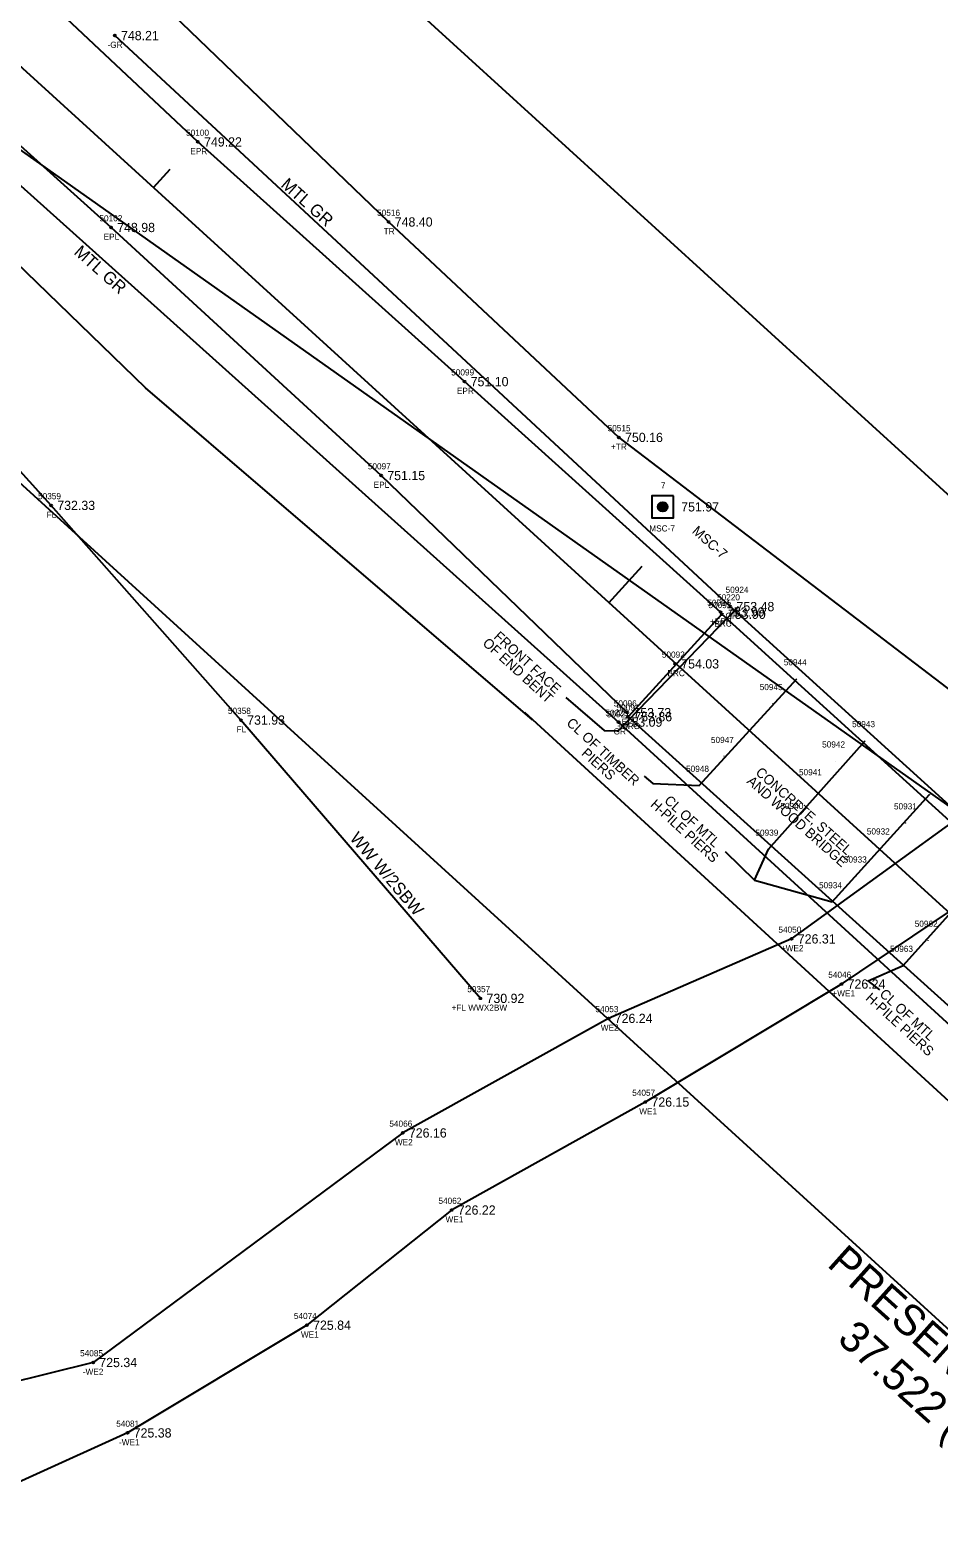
# Model space of a CAD drawing. Extents: x 1378245 to 1381654, y 996521 to 1000567.
# Drawn here: x 1379540.2 to 1379687.6, y 998853.4 to 999097.9 of the extents above; entities that cross this region are included whole.
import ezdxf

# ---------------------------------------------------------------- set-up
doc = ezdxf.new("R2010")
doc.units = 0
for name, color, linetype in [('Default', 7, 'Continuous'), ('RD_EX_Bridge', 7, 'Continuous'), ('RD_EX_Bridge_txCode', 7, 'Continuous'), ('RD_EX_Fence_Other', 7, 'Continuous'), ('RD_EX_Fence_Other_txCode', 7, 'Continuous'), ('RD_EX_GuardRail', 7, 'Continuous'), ('RD_EX_GuardRail_txCode', 7, 'Continuous'), ('RD_EX_H2O', 7, 'Continuous'), ('RD_EX_H2O_txCode', 7, 'Continuous'), ('RD_EX_Road', 7, 'Continuous'), ('RD_EX_Road_txCode', 7, 'Continuous'), ('RD_EX_RW', 7, 'Continuous'), ('RD_EX_RW_TX', 7, 'Continuous'), ('RD_EX_SU_Elec', 7, 'Continuous'), ('RD_EX_TX_Bridge_ELEV', 7, 'Continuous'), ('RD_EX_TX_Fence_Other_ELEV', 7, 'Continuous'), ('RD_EX_TX_GuardRail_ELEV', 7, 'Continuous'), ('RD_EX_TX_H2O_ELEV', 7, 'Continuous'), ('RD_EX_TX_Road_ELEV', 7, 'Continuous'), ('RD_EX_TX_VEG_ELEV', 7, 'Continuous'), ('RD_EX_VEG', 7, 'Continuous'), ('RD_EX_VEG_txCode', 7, 'Continuous'), ('RD_HC_Cl', 7, 'Continuous'), ('RD_HC_Data_Tic', 7, 'Continuous'), ('RD_HC_Survey', 7, 'Continuous'), ('RD_HC_Survey_ELEV', 7, 'Continuous'), ('RD_HC_Survey_txCode', 7, 'Continuous'), ('RD_SMD_Locator', 7, 'Continuous'), ('RD_TX_Misc1', 7, 'Continuous'), ('RD_TX_Misc2', 7, 'Continuous')]:
    doc.layers.add(name, color=color, linetype=linetype)

msp = doc.modelspace()

# ---------------------------------------------------------------- linework, layer by layer
at = {"layer": 'Default'}
for p, q in [((1379655.15, 999004.45), (1379655.14, 999004.45)), ((1379655.15, 999004.45), (1379655.15, 999004.44)), ((1379664.61, 998992.69), (1379664.59, 998992.69)), ((1379664.6, 998992.69), (1379664.6, 998992.68)), ((1379660.7, 998988.67), (1379660.68, 998988.67)), ((1379660.69, 998988.68), (1379660.69, 998988.66)), ((1379635.59, 998984.27), (1379635.57, 998984.27)), ((1379635.58, 998984.28), (1379635.58, 998984.26)), ((1379675.69, 998982.66), (1379675.67, 998982.66)), ((1379675.68, 998982.67), (1379675.68, 998982.65)), ((1379652.78, 998980.09), (1379652.76, 998980.09)), ((1379652.77, 998980.09), (1379652.77, 998980.08)), ((1379670.83, 998979.36), (1379670.81, 998979.36)), ((1379670.82, 998979.37), (1379670.82, 998979.35)), ((1379648.75, 998975.41), (1379648.73, 998975.41)), ((1379648.74, 998975.42), (1379648.74, 998975.4)), ((1379666.78, 998974.85), (1379666.76, 998974.85)), ((1379666.77, 998974.86), (1379666.77, 998974.84)), ((1379686.13, 998973.96), (1379686.11, 998973.96)), ((1379686.12, 998973.97), (1379686.12, 998973.95)), ((1379664.09, 998969.38), (1379664.07, 998969.38)), ((1379664.08, 998969.39), (1379664.08, 998969.38)), ((1379682.2, 998969.32), (1379682.18, 998969.32)), ((1379682.19, 998969.33), (1379682.19, 998969.31)), ((1379660, 998965.05), (1379659.98, 998965.05)), ((1379659.99, 998965.06), (1379659.99, 998965.04)), ((1379678.08, 998965.25), (1379678.06, 998965.25)), ((1379678.07, 998965.26), (1379678.07, 998965.24)), ((1379674.35, 998960.7), (1379674.33, 998960.7)), ((1379674.34, 998960.71), (1379674.34, 998960.69)), ((1379670.31, 998956.52), (1379670.3, 998956.52)), ((1379670.31, 998956.53), (1379670.31, 998956.51)), ((1379685.86, 998950.29), (1379685.86, 998950.27)), ((1379685.87, 998950.28), (1379685.86, 998950.28)), ((1379681.87, 998946.21), (1379681.86, 998946.21)), ((1379681.87, 998946.22), (1379681.87, 998946.2))]:
    msp.add_line(p, q, dxfattribs=at)
at = {"layer": 'RD_EX_Bridge'}
for p, q in [((1379635.58, 998984.27), (1379655.15, 999004.45)), ((1379648.74, 998975.4), (1379664.6, 998992.69)), ((1379659.99, 998965.05), (1379675.68, 998982.66)), ((1379670.31, 998956.52), (1379686.12, 998973.96)), ((1379681.87, 998946.21), (1379697.5, 998963.6))]:
    msp.add_line(p, q, dxfattribs=at)
msp.add_lwpolyline([(1379715.01, 998916.39), (1379729.96, 998932.8), (1379652.41, 999003.17), (1379637.22, 998986.55), (1379715.01, 998916.39)], dxfattribs=at)
at = {"layer": 'RD_EX_Fence_Other'}
msp.add_lwpolyline([(1379613.24, 998940.87), (1379574.4, 998986.01), (1379543.59, 999020.83), (1379505.83, 999062.54), (1379472.56, 999095.44), (1379454.3, 999112.36), (1379373.85, 999187.96), (1379325.25, 999231.37), (1379289.51, 999266.01), (1379255.48, 999295.15), (1379213.9, 999334), (1379169.28, 999374.93), (1379148.65, 999391.69), (1379140.06, 999386.4)], dxfattribs=at)
at = {"layer": 'RD_EX_GuardRail'}
for points in [[(1379497.52, 999109.58), (1379635.64, 998985.68), (1379713.53, 998914.45), (1379759.99, 998873.32)], [(1379777.52, 998892.18), (1379731.47, 998933.97), (1379653.8, 999004.42), (1379553.93, 999097.04)]]:
    msp.add_lwpolyline(points, dxfattribs=at)
at = {"layer": 'RD_EX_H2O'}
for points in [[(1379663.75, 998950.52), (1379692.38, 998971.29), (1379719.04, 999005.74), (1379767.05, 999077.47), (1379820.32, 999142.06), (1379856.78, 999184.17), (1379909.65, 999199.37), (1379968.41, 999216.31), (1380029.43, 999227.41), (1380049.41, 999276.13), (1380067, 999316.44)], [(1379671.83, 998943.2), (1379700.96, 998962.76), (1379729.37, 998999.6)], [(1379663.75, 998950.52), (1379634.04, 998937.63), (1379600.64, 998919.05), (1379550.41, 998881.81), (1379521.39, 998874.62)], [(1379671.83, 998943.2), (1379640, 998924.06), (1379608.58, 998906.54), (1379585.1, 998887.86), (1379555.99, 998870.39), (1379525.83, 998856.73)]]:
    msp.add_lwpolyline(points, dxfattribs=at)
at = {"layer": 'RD_EX_Road'}
for points in [[(1379637.07, 998987.22), (1379597.14, 999025.68), (1379553.31, 999065.91), (1379510.7, 999104.3), (1379468.49, 999142.89), (1379424.88, 999182.89), (1379377.9, 999224.84), (1379333.61, 999264.98), (1379287.28, 999307.21), (1379240.78, 999348.98)], [(1379652.22, 999003.54), (1379610.67, 999040.91), (1379567.41, 999079.79), (1379524.77, 999119.81), (1379481.79, 999158.31), (1379438.69, 999197.69), (1379392.81, 999238.63), (1379346.75, 999280.78), (1379301.8, 999321.66)]]:
    msp.add_lwpolyline(points, dxfattribs=at)
at = {"layer": 'RD_EX_RW'}
for p, q in [((1379446.02, 999244.05), (1379815.63, 998907.31)), ((1379378.68, 999170.13), (1379748.28, 998833.39))]:
    msp.add_line(p, q, dxfattribs=at)
at = {"layer": 'RD_EX_SU_Elec'}
msp.add_lwpolyline([(1378514.25, 999944.12), (1378777.7, 999831.22), (1379190.17, 999461.05), (1379403.33, 999174.04), (1379756.94, 998924.25), (1380051.16, 998659.97), (1380327.91, 998390.65), (1380546.23, 998058.37)], dxfattribs=at)
at = {"layer": 'RD_EX_VEG'}
for p, q in [((1379635.72, 999031.86), (1379746.57, 998947.26)), ((1379716.47, 998899.23), (1379620.44, 998987.26))]:
    msp.add_line(p, q, dxfattribs=at)
for points in [[(1379635.72, 999031.86), (1379598.35, 999066.81), (1379553.67, 999109.8), (1379511.83, 999151.82), (1379464.53, 999192.2), (1379415.99, 999234.77), (1379368.04, 999279.07), (1379324.89, 999312.56), (1379291.58, 999344.45), (1379199.89, 999450.8), (1379227.01, 999457.75)], [(1379621.71, 998986.05), (1379558.91, 999039.89), (1379518.45, 999079.04), (1379470.36, 999123.18), (1379409.67, 999155.52), (1379381.73, 999202.94), (1379345.95, 999233.83), (1379296.88, 999282.18), (1379264.05, 999313.51), (1379229.78, 999344.81), (1379187.41, 999381.54), (1379155.41, 999406.5), (1379144.25, 999379.18), (1379133.7, 999360.09), (1379119.62, 999335.97)]]:
    msp.add_lwpolyline(points, dxfattribs=at)
at = {"layer": 'RD_HC_Cl'}
msp.add_line((1378781.54, 999781.8), (1380217.09, 998473.92), dxfattribs=at)
at = {"layer": 'RD_HC_Data_Tic'}
for p, q in [((1379560.19, 999072.4), (1379562.89, 999075.35)), ((1379634.11, 999005.05), (1379639.5, 999010.96))]:
    msp.add_line(p, q, dxfattribs=at)
at = {"layer": 'RD_HC_Survey'}
for p, q in [((1379642.07, 999020.42), (1379642.07, 999020.78)), ((1379642.1, 999020.34), (1379642.1, 999020.87)), ((1379642.12, 999020.28), (1379642.12, 999020.93)), ((1379642.15, 999020.23), (1379642.15, 999020.98)), ((1379642.17, 999020.18), (1379642.17, 999021.02)), ((1379642.2, 999020.15), (1379642.2, 999021.05)), ((1379642.22, 999020.11), (1379642.22, 999021.09)), ((1379642.25, 999020.08), (1379642.25, 999021.12)), ((1379642.27, 999020.06), (1379642.27, 999021.14)), ((1379642.3, 999020.03), (1379642.3, 999021.17)), ((1379642.32, 999020.01), (1379642.32, 999021.19)), ((1379642.35, 999019.99), (1379642.35, 999021.21)), ((1379642.37, 999019.97), (1379642.37, 999021.23)), ((1379642.4, 999019.95), (1379642.4, 999021.25)), ((1379642.42, 999019.94), (1379642.42, 999021.26)), ((1379642.45, 999019.92), (1379642.45, 999021.28)), ((1379642.47, 999019.91), (1379642.47, 999021.29)), ((1379642.5, 999019.9), (1379642.5, 999021.3)), ((1379642.52, 999019.89), (1379642.52, 999021.32)), ((1379642.55, 999019.88), (1379642.55, 999021.33)), ((1379642.57, 999019.87), (1379642.57, 999021.33)), ((1379642.6, 999019.86), (1379642.6, 999021.34)), ((1379642.62, 999019.85), (1379642.62, 999021.35)), ((1379642.65, 999019.85), (1379642.65, 999021.36)), ((1379642.67, 999019.84), (1379642.67, 999021.36)), ((1379642.7, 999019.83), (1379642.7, 999021.37)), ((1379642.72, 999019.83), (1379642.72, 999021.37)), ((1379642.75, 999019.83), (1379642.75, 999021.37)), ((1379642.77, 999019.83), (1379642.77, 999021.38)), ((1379642.8, 999019.82), (1379642.8, 999021.38)), ((1379642.82, 999019.82), (1379642.82, 999021.38)), ((1379642.85, 999019.82), (1379642.85, 999021.38)), ((1379642.87, 999019.82), (1379642.87, 999021.38)), ((1379642.9, 999019.83), (1379642.9, 999021.38)), ((1379642.92, 999019.83), (1379642.92, 999021.37)), ((1379642.95, 999019.83), (1379642.95, 999021.37)), ((1379642.97, 999019.84), (1379642.97, 999021.36)), ((1379643, 999019.84), (1379643, 999021.36)), ((1379643.02, 999019.85), (1379643.02, 999021.35)), ((1379643.05, 999019.86), (1379643.05, 999021.35)), ((1379643.07, 999019.86), (1379643.07, 999021.34)), ((1379643.1, 999019.87), (1379643.1, 999021.33)), ((1379643.12, 999019.88), (1379643.12, 999021.32)), ((1379643.15, 999019.89), (1379643.15, 999021.31)), ((1379643.17, 999019.9), (1379643.17, 999021.3)), ((1379643.2, 999019.92), (1379643.2, 999021.29)), ((1379643.22, 999019.93), (1379643.22, 999021.27)), ((1379643.25, 999019.95), (1379643.25, 999021.26)), ((1379643.27, 999019.96), (1379643.27, 999021.24)), ((1379643.3, 999019.98), (1379643.3, 999021.22)), ((1379643.32, 999020), (1379643.32, 999021.2)), ((1379643.35, 999020.02), (1379643.35, 999021.18)), ((1379643.37, 999020.05), (1379643.37, 999021.16)), ((1379643.4, 999020.07), (1379643.4, 999021.13)), ((1379643.42, 999020.1), (1379643.42, 999021.1)), ((1379643.45, 999020.13), (1379643.45, 999021.07)), ((1379643.47, 999020.17), (1379643.47, 999021.04)), ((1379643.5, 999020.21), (1379643.5, 999021)), ((1379643.52, 999020.25), (1379643.52, 999020.95)), ((1379643.55, 999020.31), (1379643.55, 999020.9)), ((1379643.57, 999020.38), (1379643.57, 999020.83)), ((1379643.6, 999020.49), (1379643.6, 999020.71))]:
    msp.add_line(p, q, dxfattribs=at)
msp.add_lwpolyline([(1379644.6, 999022.37), (1379641.06, 999022.37), (1379641.06, 999018.83), (1379644.6, 999018.83)], close=True, dxfattribs=at)
msp.add_circle((1379642.83, 999020.6), 0.777, dxfattribs=at)
at = {"layer": 'RD_SMD_Locator'}
for centre, radius in [((1379553.93, 999097.04), 0.15), ((1379567.41, 999079.79), 0.15), ((1379598.35, 999066.81), 0.15), ((1379553.31, 999065.91), 0.15), ((1379610.67, 999040.91), 0.15), ((1379635.72, 999031.86), 0.15), ((1379597.14, 999025.68), 0.15), ((1379543.59, 999020.83), 0.15), ((1379642.83, 999020.6), 0.075), ((1379652.22, 999003.54), 0.15), ((1379652.41, 999003.17), 0.15), ((1379653.8, 999004.42), 0.15), ((1379644.84, 998995.13), 0.15), ((1379574.4, 998986.01), 0.15), ((1379637.07, 998987.22), 0.15), ((1379637.22, 998986.55), 0.15), ((1379635.64, 998985.68), 0.15), ((1379663.75, 998950.52), 0.15), ((1379671.83, 998943.2), 0.15), ((1379613.24, 998940.87), 0.15), ((1379634.04, 998937.63), 0.15), ((1379640, 998924.06), 0.15), ((1379600.64, 998919.05), 0.15), ((1379608.58, 998906.54), 0.15), ((1379585.1, 998887.86), 0.15), ((1379550.41, 998881.81), 0.15), ((1379555.99, 998870.39), 0.15)]:
    msp.add_circle(centre, radius, dxfattribs=at)
at = {"layer": 'RD_TX_Misc1'}
msp.add_line((1379657.72, 998960.05), (1379670.31, 998956.52), dxfattribs=at)
for points in [[(1379627.09, 998989.66), (1379633.34, 998984.31), (1379635.58, 998984.27)], [(1379639.82, 998976.94), (1379641.21, 998975.73), (1379648.74, 998975.4)], [(1379652.98, 998964.68), (1379657.72, 998960.05), (1379659.99, 998965.05)], [(1379678.07, 998942.26), (1379676.16, 998943.72), (1379681.87, 998946.21)]]:
    msp.add_lwpolyline(points, dxfattribs=at)

# ---------------------------------------------------------------- texts
at = {"layer": 'Default'}
for s, p in [('50924', (1379653.03, 999006.65)), ('50944', (1379662.48, 998994.89)), ('50945', (1379658.57, 998990.87)), ('50921', (1379633.75, 998986.47)), ('50943', (1379673.56, 998984.86)), ('50947', (1379650.65, 998982.29)), ('50942', (1379668.7, 998981.56)), ('50948', (1379646.62, 998977.61)), ('50941', (1379664.94, 998977.05)), ('50940', (1379661.92, 998971.58)), ('50931', (1379680.35, 998971.52)), ('50939', (1379657.87, 998967.25)), ('50932', (1379675.95, 998967.45)), ('50933', (1379672.22, 998962.9)), ('50934', (1379668.19, 998958.72)), ('50962', (1379683.72, 998952.48)), ('50963', (1379679.72, 998948.41))]:
    msp.add_text(s, height=1, dxfattribs=at).set_placement(p)
at = {"layer": 'RD_EX_Bridge_txCode'}
for s, p in [('50093', (1379650.25, 999004.17)), ('-BRC', (1379650.75, 999001.17)), ('50092', (1379642.69, 998996.13)), ('BRC', (1379643.59, 998993.13)), ('50091', (1379635.35, 998987.55)), ('+BRC', (1379635.48, 998984.55))]:
    msp.add_text(s, height=1, dxfattribs=at).set_placement(p)
at = {"layer": 'RD_EX_Fence_Other_txCode'}
for s, p in [('50359', (1379541.47, 999021.83)), ('FL', (1379542.86, 999018.83)), ('50358', (1379572.28, 998987.01)), ('FL', (1379573.67, 998984.01)), ('50357', (1379611.12, 998941.87)), ('+FL WWX2BW', (1379608.56, 998938.87))]:
    msp.add_text(s, height=1, dxfattribs=at).set_placement(p)
at = {"layer": 'RD_EX_GuardRail_txCode'}
for s, p in [('-GR', (1379552.74, 999095.04)), ('50220', (1379651.64, 999005.42)), ('GR', (1379653.02, 999002.42)), ('50225', (1379633.52, 998986.68)), ('GR', (1379634.86, 998983.68))]:
    msp.add_text(s, height=1, dxfattribs=at).set_placement(p)
at = {"layer": 'RD_EX_H2O_txCode'}
for s, p in [('54050', (1379661.6, 998951.52)), ('+WE2', (1379662, 998948.52)), ('54046', (1379669.69, 998944.2)), ('+WE1', (1379670.36, 998941.2)), ('54053', (1379631.92, 998938.63)), ('WE2', (1379632.78, 998935.63)), ('54057', (1379637.88, 998925.06)), ('WE1', (1379639.02, 998922.06)), ('54066', (1379598.47, 998920.05)), ('WE2', (1379599.37, 998917.05)), ('54062', (1379606.44, 998907.54)), ('WE1', (1379607.59, 998904.54)), ('54074', (1379582.98, 998888.86)), ('WE1', (1379584.12, 998885.86)), ('54085', (1379548.29, 998882.81)), ('-WE2', (1379548.73, 998879.81)), ('54081', (1379554.16, 998871.39)), ('-WE1', (1379554.6, 998868.39))]:
    msp.add_text(s, height=1, dxfattribs=at).set_placement(p)
at = {"layer": 'RD_EX_Road_txCode'}
for s, p in [('50100', (1379565.49, 999080.79)), ('EPR', (1379566.18, 999077.79)), ('50102', (1379551.43, 999066.91)), ('EPL', (1379552.1, 999063.91)), ('50099', (1379608.51, 999041.91)), ('EPR', (1379609.44, 999038.91)), ('50097', (1379594.98, 999026.68)), ('EPL', (1379595.93, 999023.68)), ('50094', (1379650.06, 999004.54)), ('+EPR', (1379650.5, 999001.54)), ('50096', (1379634.89, 998988.22)), ('+EPL', (1379635.37, 998985.22))]:
    msp.add_text(s, height=1, dxfattribs=at).set_placement(p)
at = {"layer": 'RD_EX_RW_TX'}
for s, p in [("PRESENT 50.0' R/W", (1379669.33, 998897.54)), ('37.522 (1964)', (1379670.97, 998885.33))]:
    msp.add_text(s, height=5, rotation=318.1047, dxfattribs=at).set_placement(p)
at = {"layer": 'RD_EX_TX_Bridge_ELEV'}
for s, p in [('753.90', (1379653.41, 999002.42)), ('754.03', (1379645.84, 998994.38)), ('753.86', (1379638.22, 998985.8))]:
    msp.add_text(s, height=1.5, dxfattribs=at).set_placement(p)
at = {"layer": 'RD_EX_TX_Fence_Other_ELEV'}
for s, p in [('732.33', (1379544.59, 999020.08)), ('731.93', (1379575.4, 998985.26)), ('730.92', (1379614.24, 998940.12))]:
    msp.add_text(s, height=1.5, dxfattribs=at).set_placement(p)
at = {"layer": 'RD_EX_TX_GuardRail_ELEV'}
for s, p in [('748.21', (1379554.93, 999096.29)), ('753.48', (1379654.8, 999003.67)), ('753.09', (1379636.64, 998984.93))]:
    msp.add_text(s, height=1.5, dxfattribs=at).set_placement(p)
at = {"layer": 'RD_EX_TX_H2O_ELEV'}
for s, p in [('726.31', (1379664.75, 998949.77)), ('726.24', (1379672.83, 998942.45)), ('726.24', (1379635.04, 998936.88)), ('726.15', (1379641, 998923.31)), ('726.16', (1379601.64, 998918.3)), ('726.22', (1379609.58, 998905.79)), ('725.84', (1379586.1, 998887.11)), ('725.34', (1379551.41, 998881.06)), ('725.38', (1379556.99, 998869.64))]:
    msp.add_text(s, height=1.5, dxfattribs=at).set_placement(p)
at = {"layer": 'RD_EX_TX_Road_ELEV'}
for s, p in [('749.22', (1379568.41, 999079.04)), ('748.98', (1379554.31, 999065.16)), ('751.10', (1379611.67, 999040.16)), ('751.15', (1379598.14, 999024.93)), ('753.99', (1379653.22, 999002.79)), ('753.73', (1379638.07, 998986.47))]:
    msp.add_text(s, height=1.5, dxfattribs=at).set_placement(p)
at = {"layer": 'RD_EX_TX_VEG_ELEV'}
for s, p in [('748.40', (1379599.35, 999066.06)), ('750.16', (1379636.72, 999031.11))]:
    msp.add_text(s, height=1.5, dxfattribs=at).set_placement(p)
at = {"layer": 'RD_EX_VEG_txCode'}
for s, p in [('50516', (1379596.49, 999067.81)), ('TR', (1379597.55, 999064.81)), ('50515', (1379633.89, 999032.86)), ('+TR', (1379634.44, 999029.86))]:
    msp.add_text(s, height=1, dxfattribs=at).set_placement(p)
at = {"layer": 'RD_HC_Survey_ELEV'}
msp.add_text('751.97', height=1.5, dxfattribs=at).set_placement((1379645.83, 999019.85))
msp.add_text('751.97', height=1.5, dxfattribs=at).set_placement((1379645.83, 999019.85))
at = {"layer": 'RD_HC_Survey_txCode'}
for s, p in [('7', (1379642.54, 999023.6)), ('7', (1379642.54, 999023.6)), ('MSC-7', (1379640.65, 999016.6)), ('MSC-7', (1379640.65, 999016.6))]:
    msp.add_text(s, height=1, dxfattribs=at).set_placement(p)
at = {"layer": 'RD_TX_Misc1'}
for s, rotation, p in [('MSC-7', 318.2461, (1379647.48, 999016.48)), ('OF END BENT', 317.6383, (1379613.49, 998998.32)), ('FRONT FACE', 317.6383, (1379615.31, 998999.38)), ('CL OF TIMBER', 317.6383, (1379627.1, 998985.36)), (' PIERS', 317.6383, (1379629.07, 998980.85)), ('AND WOOD BRIDGE', 318.2461, (1379656.35, 998975.92)), ('CONCRETE, STEEL,', 318.2461, (1379657.78, 998977.33)), (' H-PILE PIERS', 317.6383, (1379640.26, 998972.53)), ('CL OF MTL', 317.6383, (1379642.96, 998972.77)), ('CL OF MTL', 317.6383, (1379677.89, 998941.4)), (' H-PILE PIERS', 317.6383, (1379675.19, 998941.15))]:
    msp.add_text(s, height=1.6, rotation=rotation, dxfattribs=at).set_placement(p)
at = {"layer": 'RD_TX_Misc2'}
for s, rotation, p in [('MTL GR', 318.2461, (1379580.73, 999072.64)), ('MTL GR', 318.2461, (1379547.16, 999061.71)), ('WW W/2SBW', 310.265, (1379591.94, 998966.78))]:
    msp.add_text(s, height=2, rotation=rotation, dxfattribs=at).set_placement(p)

doc.saveas('drawing.dxf')
